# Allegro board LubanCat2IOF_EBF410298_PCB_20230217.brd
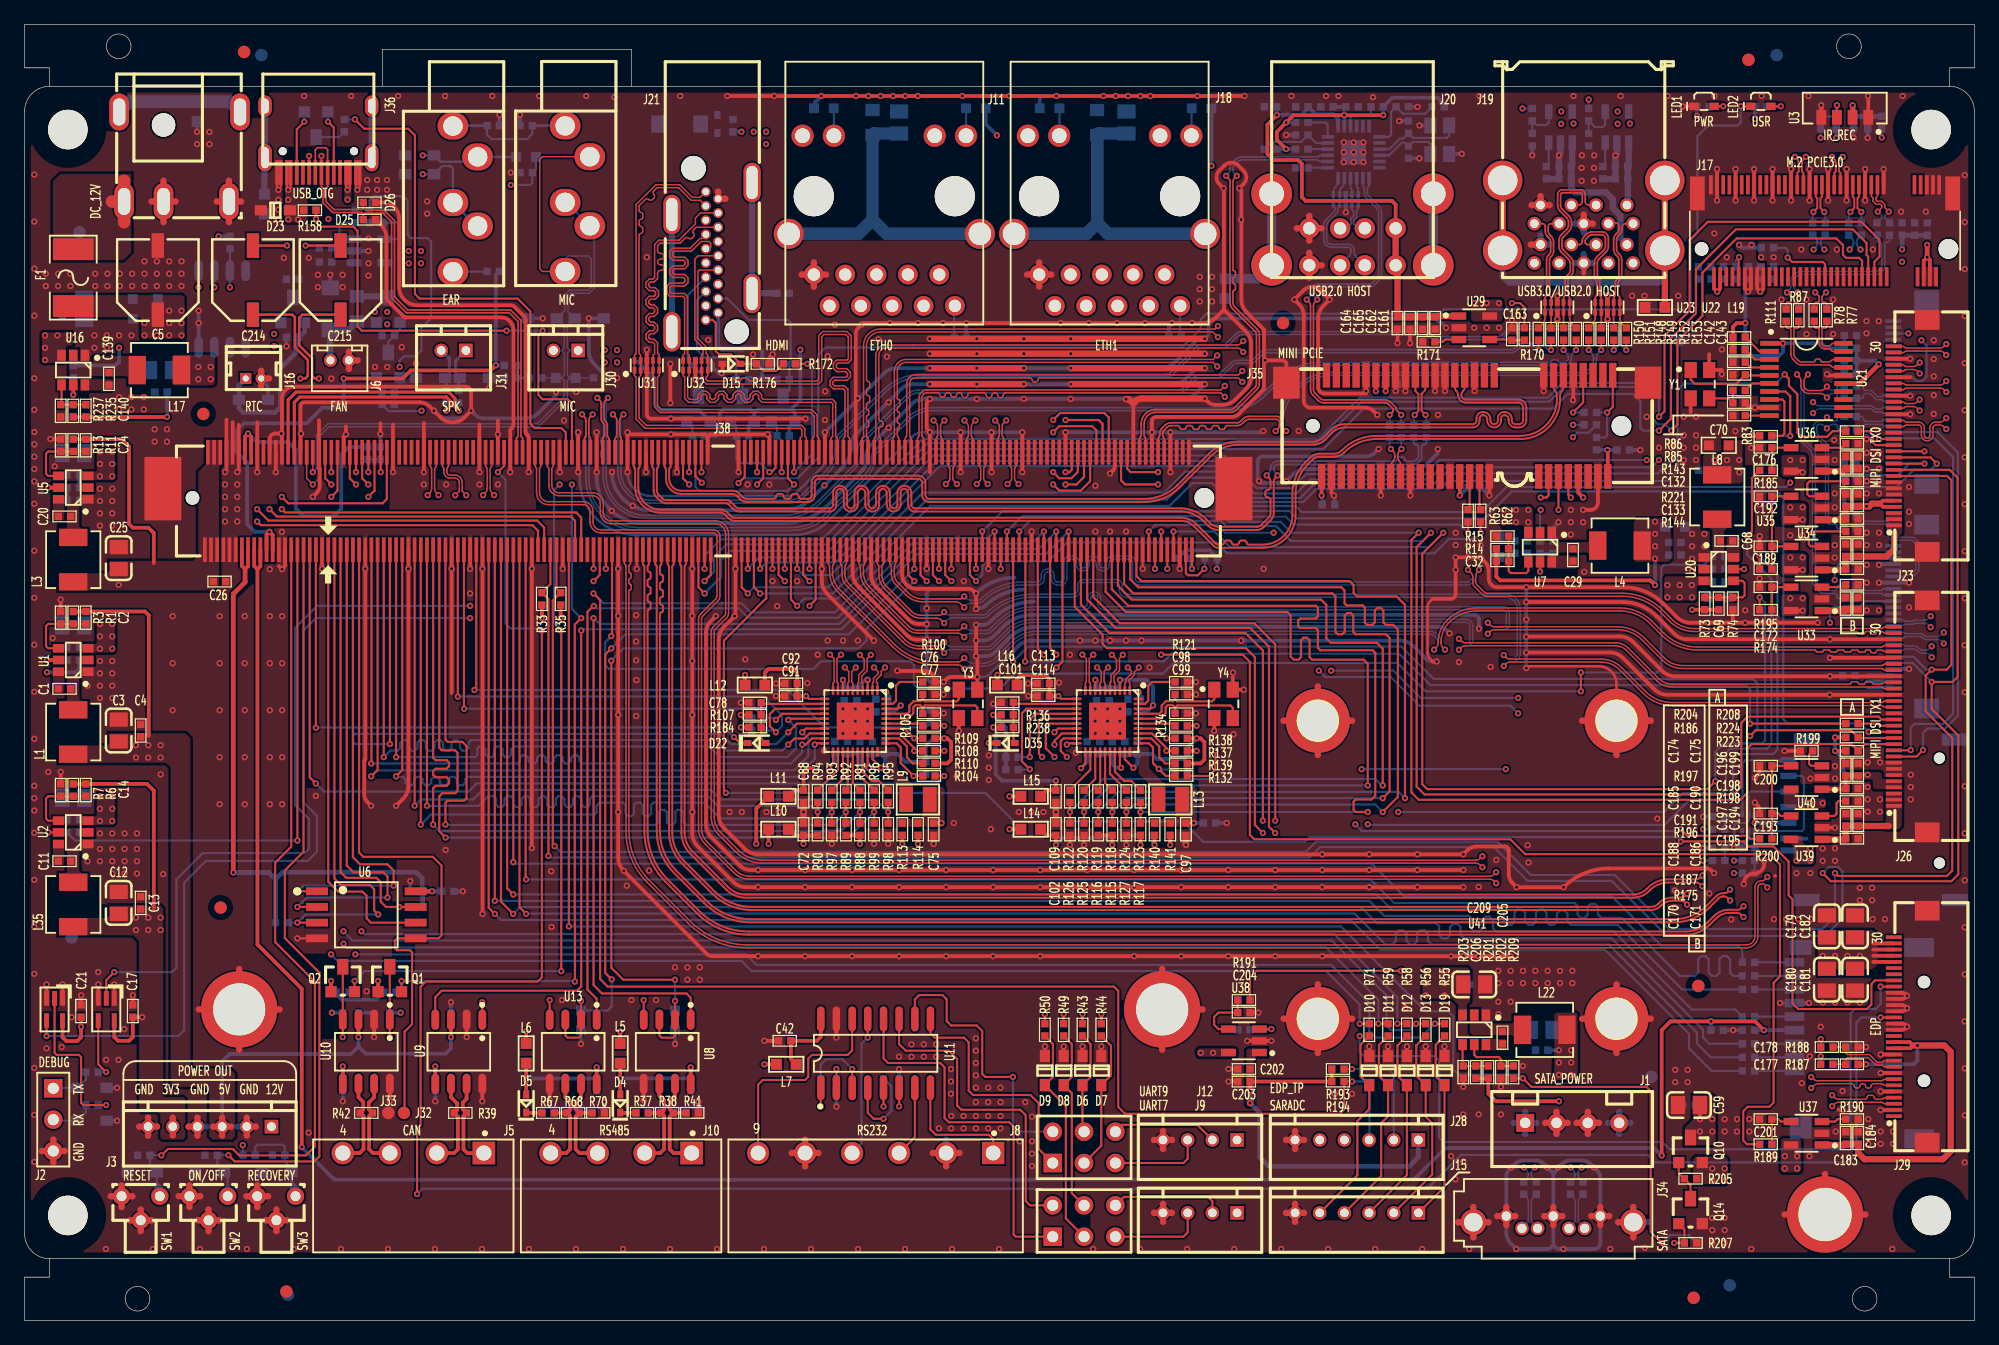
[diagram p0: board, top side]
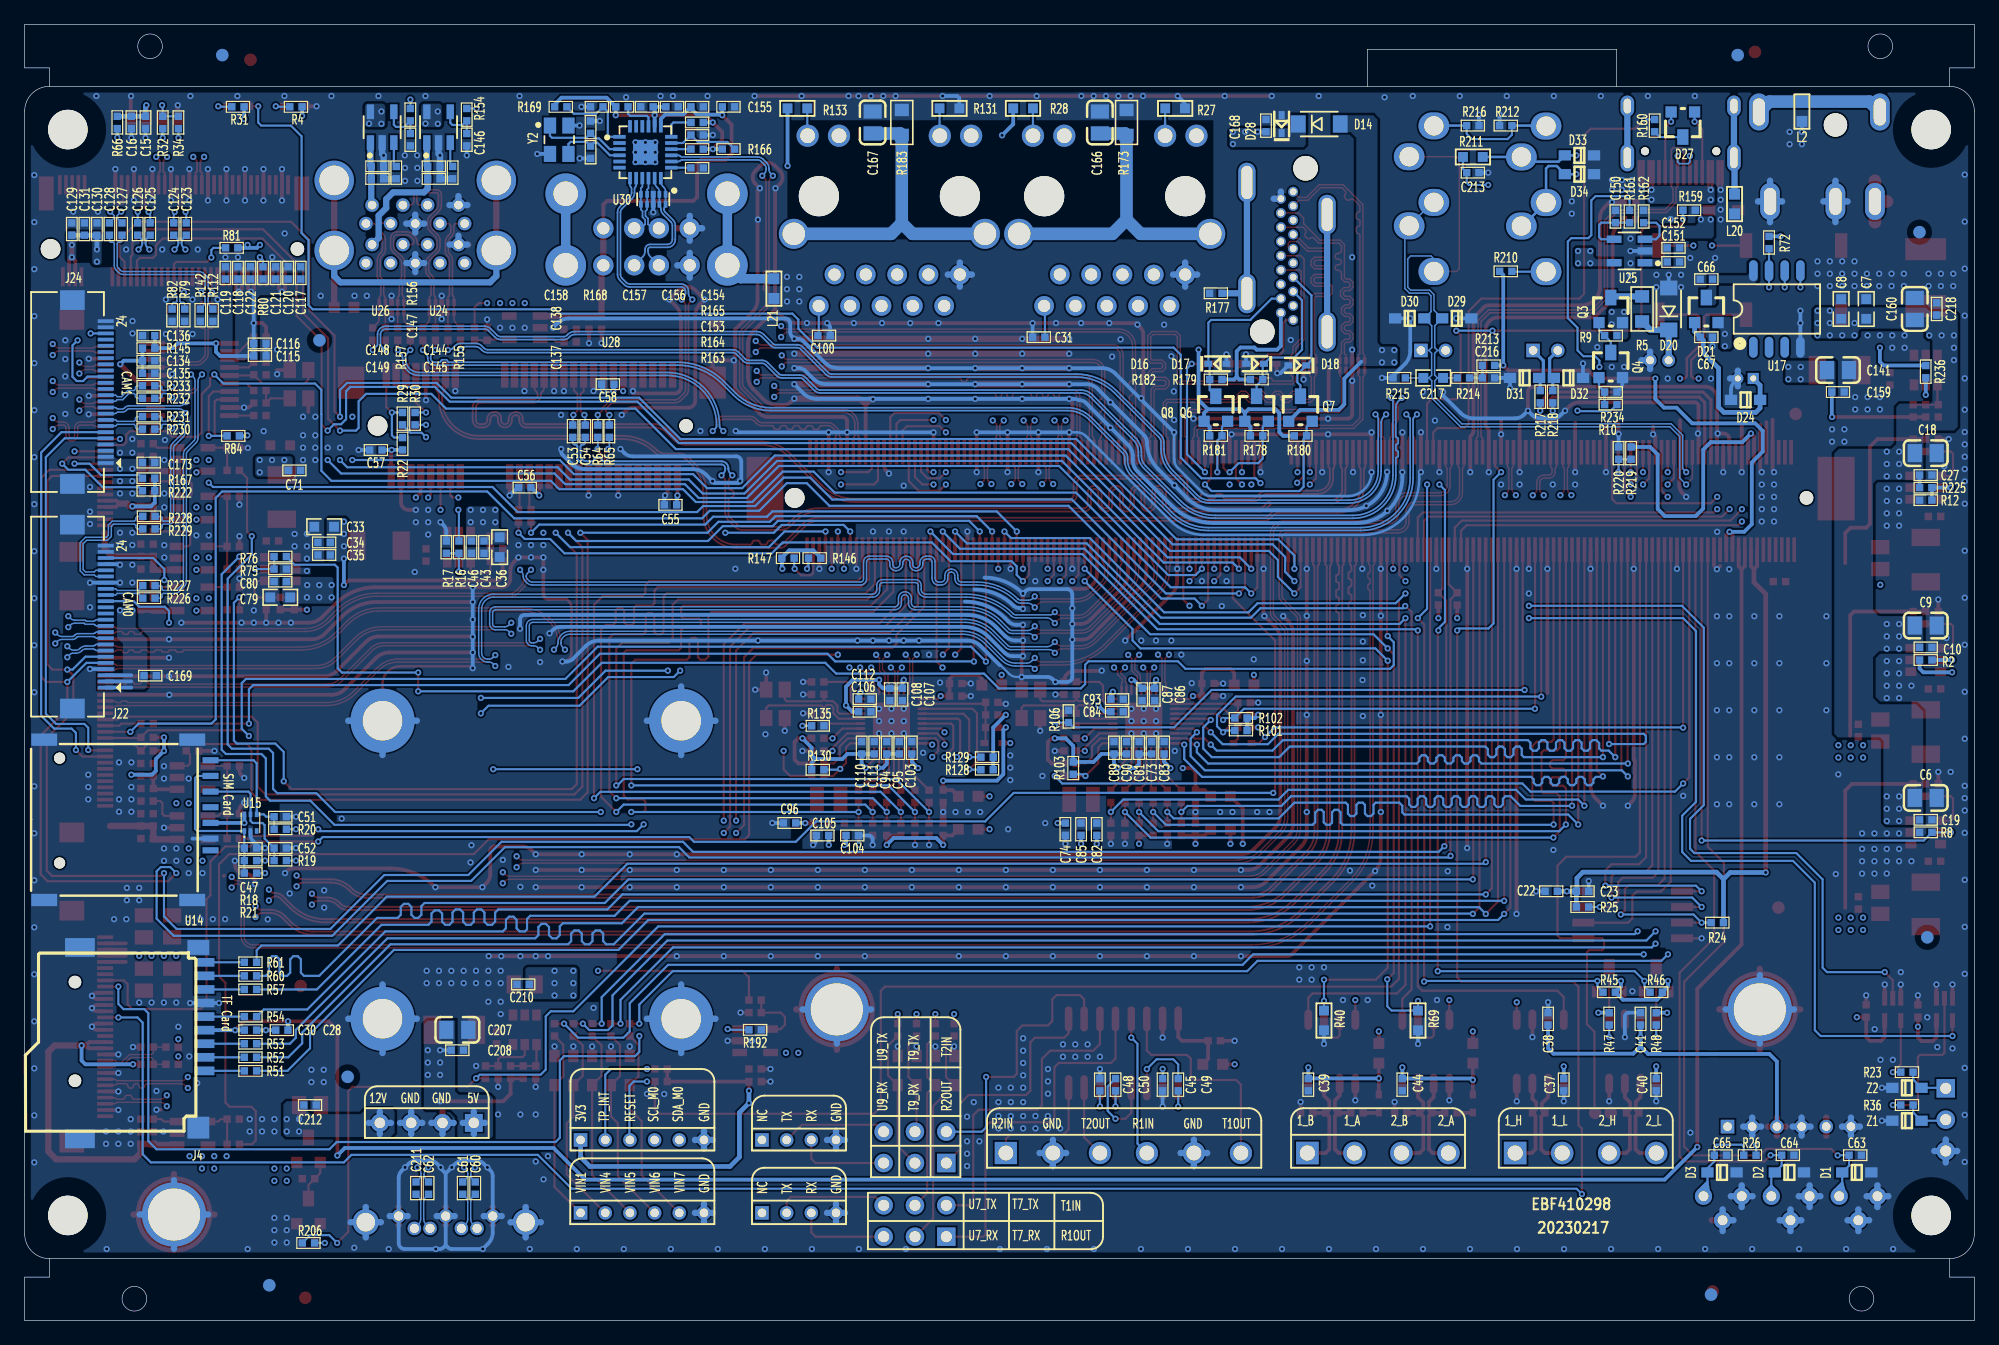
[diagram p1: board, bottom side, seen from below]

Outline 158 x 105 mm; copper layers: TOP, GND02, ART03, ART04, PWR05, BOTTOM. Coordinates in mm from the lower left corner of the outline.
Outline path: circle c7.62,103.25 r1 ; circle c9.14,1.75 r1 ; circle c147.84,103.25 r1 ; circle c149.11,1.75 r1 ; 2,100 arc(0.59,99.41) 0,98 0,7 arc(0.59,5.59) 2,5 ; 2,100 2,101.5 0,101.5 0,105 158,105 158,101.5 156,101.5 156,100 ; 2,100 156,100 ; 2,5 2,3.5 0,3.5 0,0 158,0 158,3.5 156,3.5 156,5 ; 2,5 156,5 ; 156,5 arc(157.41,5.59) 158,7 158,98 arc(157.41,99.41) 156,100 ; 28.99,100 28.99,103 49.18,103 49.18,100

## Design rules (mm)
net group DIFF_MDI0_PHY0: nets MDIN0_PHY0 MDIP0_PHY0
net group DIFF_MDI0_PHY1: nets MDIN0_PHY1 MDIP0_PHY1
net group DIFF_MDI1_PHY0: nets MDIN1_PHY0 MDIP1_PHY0
net group DIFF_MDI1_PHY1: nets MDIN1_PHY1 MDIP1_PHY1
net group DIFF_MDI2_PHY0: nets MDIN2_PHY0 MDIP2_PHY0
net group DIFF_MDI2_PHY1: nets MDIN2_PHY1 MDIP2_PHY1
net group DIFF_MDI3_PHY0: nets MDIN3_PHY0 MDIP3_PHY0
net group DIFF_MDI3_PHY1: nets MDIN3_PHY1 MDIP3_PHY1
net group DIFF_SATA0RX: nets SATA0RXN SATA0RXP
net group DIFF_SATA0TX: nets SATA0TXN SATA0TXP
net group DIFF_USB2_HOST3_D: nets USB2_HOST3_DM USB2_HOST3_DP
net group DIFF_USB3_HOST1_SSTX: nets USB3_HOST1_SSTXN USB3_HOST1_SSTXP
net group DIFF_USB3_OTG0_D: nets USB3_OTG0_DM USB3_OTG0_DP
net group DIFF_USB30_TX: nets USB30_TXN USB30_TXP
net group DIFF_USB_HUB_D1: nets USB_HUB_DM1 USB_HUB_DP1
net group DIFF_USB_HUB_D2: nets USB_HUB_DM2 USB_HUB_DP2
net group EDP_AUXN: nets EDP_AUXN EDP_TX_AUXN
net group EDP_AUXP: nets EDP_AUXP EDP_TX_AUXP
net group GMAC0_RXCLK: nets GMAC0_RXCLK N15580037
net group GMAC0_RXD0: nets GMAC0_RXD0 N15580021
net group GMAC0_RXD1: nets GMAC0_RXD1 N15580025
net group GMAC0_RXD2: nets GMAC0_RXD2 N15580029
net group GMAC0_RXD3: nets GMAC0_RXD3 N15580033
net group GMAC0_RXDV_CRS: nets GMAC0_RXDV_CRS N15580041
net group GMAC1_RXCLK_M1: nets GMAC1_RXCLK_M1 N15599549
net group GMAC1_RXD0_M1: nets GMAC1_RXD0_M1 N15599533
net group GMAC1_RXD1_M1: nets GMAC1_RXD1_M1 N15599537
net group GMAC1_RXD2_M1: nets GMAC1_RXD2_M1 N15599541
net group GMAC1_RXD3_M1: nets GMAC1_RXD3_M1 N15599545
net group GMAC1_RXDV_CRS_M1: nets GMAC1_RXDV_CRS_M1 N15599553
net group MIC1_IN: nets MIC1_INN MIC1_INP
net group N17639713: nets N17639713 N17697748
net group PCIE20_CLKREQN_M1: nets N17411326 PCIE20_CLKREQN_M1
net group PCIE20_TXN: nets PCIE20_TXN PE_TXN
net group PCIE20_TXP: nets PCIE20_TXP PE_TXP
net group PCIE20_WAKEN_M1: nets N17411312 PCIE20_WAKEN_M1
net group PCIE30_REFCLKN_IN: nets N17639523 PCIE30_REFCLKN_IN
net group PCIE30_REFCLKP_IN: nets N17639486 PCIE30_REFCLKP_IN
net group PCIE30_TX0N: nets PCIE30_TX0N PETN0
net group PCIE30_TX0P: nets PCIE30_TX0P PETP0
net group PCIE30_TX1N: nets PCIE30_TX1N PETN1
net group PCIE30_TX1P: nets PCIE30_TX1P PETP1
net group PWM3_IR: nets N17536407 PWM3_IR
net group SDMMC0_CLK: nets N17407474 SDMMC0_CLK
net group SDMMC0_CMD: nets N17407476 SDMMC0_CMD
net group SDMMC0_D0: nets N17407472 SDMMC0_D0
net group SDMMC0_D1: nets N17407480 SDMMC0_D1
net group SDMMC0_D2: nets N17407470 SDMMC0_D2
net group SDMMC0_D3: nets N17407478 SDMMC0_D3
net group USB20_DM1: nets USB2_HOST2_DM USB20_DM1
net group USB20_DP1: nets USB2_HOST2_DP USB20_DP1
net group USB30_DM: nets USB3_HOST1_DM USB30_DM
net group USB30_DP: nets USB3_HOST1_DP USB30_DP
net group USB30_RXN: nets USB3_HOST1_SSRXN USB30_RXN
net group USB30_RXP: nets USB3_HOST1_SSRXP USB30_RXP
net group USB_HUB_DM3: nets N17411507 USB_HUB_DM3
net group USB_HUB_DP3: nets N17411481 USB_HUB_DP3
net group ADC: nets SARADC_VIN1 SARADC_VIN4 SARADC_VIN5 SARADC_VIN6 SARADC_VIN7
net group C_EDP: nets EDP_TX_D0N EDP_TX_D0P EDP_TX_D1N EDP_TX_D1P
net group C_HDMI: nets HDMI_TX0N_PORT HDMI_TX0P_PORT HDMI_TX1N_PORT HDMI_TX1P_PORT HDMI_TX2N_PORT HDMI_TX2P_PORT HDMI_TXCLKN_PORT HDMI_TXCLKP_PORT
net group C_MIPI_DSI_0-3: nets MIPI_DSI_TX0_CLKN MIPI_DSI_TX0_CLKP MIPI_DSI_TX0_D0N MIPI_DSI_TX0_D0P MIPI_DSI_TX0_D1P MIPI_DSI_TX0_D2N MIPI_DSI_TX0_D2P MIPI_DSI_TX0_D3N MIPI_DSI_TX0_D3P
net group C_MIPI_DSI_TX0-3: nets MIPI_DSI_TX1_CLKN MIPI_DSI_TX1_CLKP MIPI_DSI_TX1_D0N MIPI_DSI_TX1_D0P MIPI_DSI_TX1_D1N MIPI_DSI_TX1_D1P MIPI_DSI_TX1_D2N MIPI_DSI_TX1_D2P MIPI_DSI_TX1_D3N MIPI_DSI_TX1_D3P
net group C_MIPICSI: nets MIPI_CSI_RX_CLK0N MIPI_CSI_RX_CLK0P MIPI_CSI_RX_CLK1N MIPI_CSI_RX_CLK1P MIPI_CSI_RX_D0N MIPI_CSI_RX_D0P MIPI_CSI_RX_D1N MIPI_CSI_RX_D1P
net group C_PCLE3R0: nets PCIE30_RX0N PCIE30_RX0P PCIE30_RX1N PCIE30_RX1P
net group GMAC0_TXD0-3: nets GMAC0_TXCLK GMAC0_TXD0 GMAC0_TXD1 GMAC0_TXD2 GMAC0_TXD3 GMAC0_TXEN
net group M_MIPI_DSI_0-3: nets MIPI_DSI_TX0_D1N
net group MIPI_CSI_RX_D2N: nets MIPI_CSI_RX_D2N N17546373 N17737043
net group MIPI_CSI_RX_D2P: nets MIPI_CSI_RX_D2P N17546411 N17737040
net group MIPI_CSI_RX_D3N: nets MIPI_CSI_RX_D3N N17546367 N17737138
net group MIPI_CSI_RX_D3P: nets MIPI_CSI_RX_D3P N17546399 N17737126
net group PCIE: nets PCIE20_REFCLKN PCIE20_REFCLKP PCIE20_RXN PCIE20_RXP
net group PWR: nets 1V05_AVDD_PHY0 1V05_AVDD_PHY1 1V05_DVDD_PHY0 1V05_DVDD_PHY1 1V8_DVDD_PHY0 1V8_DVDD_PHY1 3V3_AVDD_PHY0 3V3_AVDD_PHY1 3V3_DVDD_PHY0 3V3_DVDD_PHY1 HUB_3V3 RS232_3V3 RS485_2_3V3 SIM_VDD VCC3V3_SD VCC5V0_USB20_HOST2 VCC5V0_USB20_HUB VCC5V0_USB30_HOST VCC_1V8 VCCA_1V8 VCCIO_ACODEC VDD_3V3_EDP_LCD VDD_LCD0_3V3
net group REFCLKN: nets N17639617 REF_CLKN REFCLKN
net group REFCLKP: nets N17639615 REF_CLKP REFCLKP
net group SD: nets SDMMC0_DET

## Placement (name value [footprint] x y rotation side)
C1  0.1uF  [C0402]  3.23 51.18 0 top
C2  NC  [C0402]  4.95 56.94 90 top
C3  22uF  [C0805]  7.62 47.8 90 top
C4  0.1uF  [C0402]  9.4 47.8 90 top
C5  100uF  [EC6P3]  10.79 84.3 180 top
C6  22uF  [C0805]  3.94 42.34 180 bottom
C7  4.7uF  [C0603]  8.76 81.96 90 bottom
C8  0.1uF  [C0603]  10.79 81.96 90 bottom
C9  22uF  [C0805]  3.94 56.31 180 bottom
C10  0.1uF  [C0402]  3.94 54.53 180 bottom
C11  0.1uF  [C0402]  3.23 37.21 0 top
C12  22uF  [C0805]  7.62 33.83 90 top
C13  0.1uF  [C0402]  9.4 33.83 90 top
C14  NC  [C0402]  4.95 42.97 90 top
C15  0.1uF  [C0402]  148.21 97.07 270 bottom
C16  4.7uF  [C0402]  149.35 97.07 270 bottom
C17  0.1uF  [C0402]  8.76 25.07 90 top
C18  22uF  [C0805]  3.94 70.28 180 bottom
C19  0.1uF  [C0402]  3.94 40.56 180 bottom
C20  0.1uF  [C0402]  3.23 65.15 0 top
C21  0.1uF  [C0402]  4.57 25.07 90 top
C22  10uF  [C0402]  34.29 34.77 0 bottom
C23  0.1uF  [C0402]  31.75 34.77 180 bottom
C24  NC  [C0402]  4.95 70.91 90 top
C25  22uF  [C0805]  7.62 61.77 90 top
C26  0.1uF  [C0402]  15.79 59.87 0 top
C27  0.1uF  [C0402]  3.94 68.5 180 bottom
C28  10uF  [C0402]  137.16 23.52 0 bottom
C29  0.1uF  [C0402]  125.48 62.02 270 top
C30  0.1uF  [C0402]  139.7 23.52 180 bottom
C31  0.1uF  [C0402]  75.82 79.68 0 bottom
C32  NC  [C0402]  119.76 61.51 0 top
C33  22uF  [C0603]  133.73 64.31 0 bottom
C34  1uF  [C0402]  133.73 63.04 0 bottom
C35  0.1uF  [C0402]  133.73 62.02 0 bottom
C36  22uF  [C0603]  119.51 62.66 270 bottom
C37  0.1uF  [C0402]  33.27 19.1 270 bottom
C38  0.1uF  [C0402]  34.54 24.43 90 bottom
C39  0.1uF  [C0402]  53.98 19.1 270 bottom
C40  0.1uF  [C0402]  25.78 19.1 270 bottom
C41  0.1uF  [C0402]  27.05 24.43 90 bottom
C42  0.1uF  [C0402]  61.59 22.65 180 top
C43  10uF  [C0402]  120.78 62.66 270 bottom
C44  0.1uF  [C0402]  46.35 19.1 270 bottom
C45  0.1uF  [C0402]  65.79 19.1 270 bottom
C46  0.1uF  [C0402]  121.79 62.66 270 bottom
C47  33pF  [C0402]  139.7 38.27 180 bottom
C48  0.1uF  [C0402]  70.87 19.1 90 bottom
C49  0.1uF  [C0402]  64.52 19.1 270 bottom
C50  0.1uF  [C0402]  69.6 19.1 90 bottom
C51  33pF  [C0402]  137.29 40.81 180 bottom
C52  33pF  [C0402]  137.29 38.27 180 bottom
C53  0.1uF  [C0402]  113.59 72.06 90 bottom
C54  0.1uF  [C0402]  112.57 72.06 90 bottom
C55  0.1uF  [C0402]  105.66 66.09 0 bottom
C56  0.1uF  [C0402]  117.47 67.48 0 bottom
C57  0.1uF  [C0402]  129.54 70.53 0 bottom
C58  0.1uF  [C0402]  110.74 75.87 0 bottom
C59  22uF  [C0805]  134.87 17.45 180 top
C60  10nF  [C0402]  121.49 10.71 270 bottom
C61  10nF  [C0402]  122.5 10.71 270 bottom
C62  10nF  [C0402]  125.27 10.71 270 bottom
C63  0.1uF  [C0402]  9.65 13.38 180 bottom
C64  0.1uF  [C0402]  15.11 13.38 180 bottom
C65  0.1uF  [C0402]  20.57 13.38 180 bottom
C66  0.1uF  [C0402]  21.72 84.37 0 bottom
C67  10uF  [C0402]  21.72 79.68 180 bottom
C68  0.1uF  [C0402]  137.92 63.17 180 top
C69  NC  [C0402]  137.29 58.09 270 top
C70  22uF  [C0603]  137.29 70.91 180 top
C71  0.1uF  [C0402]  136.14 68.88 180 bottom
C72  0.1uF  [C0402]  63.12 39.8 90 top
C73  0.1uF  [C0402]  66.67 46.4 90 bottom
C74  0.1uF  [C0402]  73.66 39.8 270 bottom
C75  4.7uF  [C0402]  73.66 39.8 270 top
C76  18pF  [C0402]  73.28 50.72 0 top
C77  18pF  [C0402]  73.28 49.2 0 top
C78  0.1uF  [C0402]  59.18 50.06 180 top
C79  22uF  [C0603]  137.29 58.59 0 bottom
C80  0.1uF  [C0402]  137.29 59.86 0 bottom
C81  0.1uF  [C0402]  67.69 46.4 90 bottom
C82  0.1uF  [C0402]  71.12 39.8 90 bottom
C83  0.1uF  [C0402]  65.66 46.4 90 bottom
C84  0.1uF  [C0402]  69.47 49.32 180 bottom
C85  0.1uF  [C0402]  72.39 39.8 90 bottom
C86  0.1uF  [C0402]  66.42 50.72 270 bottom
C87  0.1uF  [C0402]  67.44 50.72 270 bottom
C88  0.1uF  [C0402]  63.12 42.46 270 top
C89  0.1uF  [C0402]  69.72 46.4 90 bottom
C90  0.1uF  [C0402]  68.71 46.4 90 bottom
C91  0.1uF  [C0402]  62.1 50.59 180 top
C92  0.1uF  [C0402]  62.1 51.61 180 top
C93  0.1uF  [C0402]  69.47 50.34 180 bottom
C94  0.1uF  [C0402]  88.14 46.4 90 bottom
C95  0.1uF  [C0402]  87.12 46.4 90 bottom
C96  0.1uF  [C0402]  96.01 40.31 0 bottom
C97  4.7uF  [C0402]  94.11 39.8 270 top
C98  18pF  [C0402]  93.73 50.72 0 top
C99  18pF  [C0402]  93.73 49.2 0 top
C100  0.1uF  [C0402]  93.22 79.8 180 bottom
C101  0.1uF  [C0402]  79.63 50.08 180 top
C102  0.1uF  [C0402]  83.57 39.8 90 top
C103  0.1uF  [C0402]  86.11 46.4 90 bottom
C104  0.1uF  [C0402]  90.93 39.29 180 bottom
C105  0.1uF  [C0402]  93.34 39.29 0 bottom
C106  0.1uF  [C0402]  89.92 49.32 180 bottom
C107  0.1uF  [C0402]  86.87 50.72 270 bottom
C108  0.1uF  [C0402]  87.88 50.72 270 bottom
C109  0.1uF  [C0402]  83.57 42.46 270 top
C110  0.1uF  [C0402]  90.17 46.4 90 bottom
C111  0.1uF  [C0402]  89.15 46.4 90 bottom
C112  0.1uF  [C0402]  89.92 50.34 180 bottom
C113  0.1uF  [C0402]  82.55 51.61 180 top
C114  0.1uF  [C0402]  82.55 50.59 180 top
C115  1uF  [C0402]  138.94 78.15 180 bottom
C116  0.1uF  [C0402]  138.94 79.17 180 bottom
C117  0.1uF  [C0402]  135.64 84.88 90 bottom
C118  0.1uF  [C0402]  140.72 84.88 90 bottom
C119  0.1uF  [C0402]  141.73 84.88 90 bottom
C120  0.1uF  [C0402]  136.65 84.88 90 bottom
C121  0.1uF  [C0402]  137.67 84.88 90 bottom
C122  0.1uF  [C0402]  139.7 84.88 90 bottom
C123  0.22uF  [C0402]  144.91 88.44 90 bottom
C124  0.22uF  [C0402]  145.92 88.44 90 bottom
C125  0.22uF  [C0402]  147.83 88.44 90 bottom
C126  0.22uF  [C0402]  148.84 88.44 90 bottom
C127  0.22uF  [C0402]  150.11 88.44 90 bottom
C128  0.22uF  [C0402]  151.13 88.44 90 bottom
C129  0.1uF  [C0402]  154.18 88.44 90 bottom
C130  0.1uF  [C0402]  152.15 88.44 90 bottom
C131  0.1uF  [C0402]  153.16 88.44 90 bottom
C132  18pF  [C0402]  138.94 76.63 180 top
C133  18pF  [C0402]  138.94 74.34 0 top
C134  0.1uF  [C0402]  147.96 77.77 180 bottom
C135  1uF  [C0402]  147.96 76.75 180 bottom
C136  4.7uF  [C0402]  147.96 79.8 0 bottom
C137  NC  [C0402]  112.14 94.66 270 bottom
C138  NC  [C0402]  112.14 96.69 90 bottom
C139  0.1uF  [C0402]  6.83 76.3 90 top
C140  NC  [C0402]  4.95 73.71 270 top
C141  22uF  [C0805]  11.05 77.01 180 bottom
C142  0.1uF  [C0402]  128.78 79.93 270 top
C143  0.1uF  [C0402]  129.79 79.93 270 top
C144  10uF  [C0402]  124.84 93.52 180 bottom
C145  0.1uF  [C0402]  124.84 92.5 180 bottom
C146  0.1uF  [C0402]  122.17 95.68 270 bottom
C147  0.1uF  [C0402]  126.75 95.68 270 bottom
C148  10uF  [C0402]  129.41 93.52 180 bottom
C149  0.1uF  [C0402]  129.41 92.5 180 bottom
C150  0.1uF  [C0402]  29.08 89.45 90 bottom
C151  10uF  [C0402]  24.38 85.77 180 bottom
C152  0.1uF  [C0402]  24.38 86.91 180 bottom
C153  0.1uF  [C0402]  103.5 96.06 180 bottom
C154  10uF  [C0402]  103.5 98.34 180 bottom
C155  0.1uF  [C0402]  100.97 98.34 180 bottom
C156  0.1uF  [C0402]  105.54 98.34 180 bottom
C157  10uF  [C0402]  107.57 98.34 0 bottom
C158  10nF  [C0402]  111.63 98.34 0 bottom
C159  0.1uF  [C0402]  11.05 75.23 180 bottom
C160  22uF  [C0805]  4.83 81.96 90 bottom
C161  10uF  [C0402]  114.3 80.82 270 top
C162  0.1uF  [C0402]  113.28 80.82 270 top
C163  0.1uF  [C0402]  120.52 79.93 90 top
C164  1uF  [C0402]  111.25 80.82 270 top
C165  1uF  [C0402]  112.27 80.82 270 top
C166  1nF  [C0805]  70.87 97.07 90 bottom
C167  1nF  [C0805]  89.28 97.07 90 bottom
C168  1uF  [C0402]  57.4 96.82 90 bottom
C169  10uF  [C0402]  147.83 52.24 180 bottom
C170  10uF  [C0402]  147.57 58.09 90 top
C171  0.1uF  [C0402]  148.59 58.09 90 top
C172  0.1uF  [C0402]  141.1 59.42 180 top
C173  10uF  [C0402]  147.96 69.52 180 bottom
C174  10uF  [C0402]  147.57 69.52 90 top
C175  0.1uF  [C0402]  148.59 69.52 90 top
C176  0.1uF  [C0402]  141.1 70.72 180 top
C177  0.1uF  [C0402]  146.05 20.75 0 top
C178  0.1uF  [C0402]  146.05 22.14 0 top
C179  10uF  [C0805]  146.05 31.92 90 top
C180  10uF  [C0805]  146.05 27.61 270 top
C181  10uF  [C0805]  148.34 27.61 270 top
C182  10uF  [C0805]  148.34 31.92 90 top
C183  10uF  [C0402]  147.57 14.78 90 top
C184  0.1uF  [C0402]  148.59 14.78 90 top
C185  0.1uF  [C0402]  147.57 66.47 90 top
C186  10uF  [C0402]  148.59 62.4 90 top
C187  10uF  [C0402]  148.08 60.88 0 top
C188  0.1uF  [C0402]  147.57 62.4 90 top
C189  0.1uF  [C0402]  141.1 62.72 180 top
C190  10uF  [C0402]  148.59 66.47 90 top
C191  0.1uF  [C0402]  148.08 64.94 0 top
C192  0.1uF  [C0402]  141.1 66.78 180 top
C193  0.1uF  [C0402]  141.1 41.07 180 top
C194  10uF  [C0402]  148.59 40.56 90 top
C195  0.1uF  [C0402]  148.08 39.04 0 top
C196  0.1uF  [C0402]  147.57 44.62 90 top
C197  10uF  [C0402]  147.57 40.56 90 top
C198  0.1uF  [C0402]  148.08 43.1 0 top
C199  10uF  [C0402]  148.59 44.62 90 top
C200  0.1uF  [C0402]  141.1 44.94 180 top
C201  0.1uF  [C0402]  141.1 16.3 180 top
C202  10uF  [C0402]  98.81 20.37 180 top
C203  0.1uF  [C0402]  98.81 19.35 180 top
C204  0.1uF  [C0402]  98.81 24.94 0 top
C205  0.1uF  [C0402]  119.76 22.91 90 top
C206  NC  [C0402]  117.6 20.11 270 top
C207  22uF  [C0805]  122.94 23.54 180 bottom
C208  0.1uF  [C0402]  122.94 21.89 180 bottom
C209  22uF  [C0805]  117.47 27.22 0 top
C210  0.1uF  [C0402]  117.6 27.22 0 bottom
C211  10nF  [C0402]  126.29 10.71 270 bottom
C212  0.1uF  [C0402]  134.87 17.45 180 bottom
C213  1uF  [C0402]  40.64 93.01 180 bottom
C214  220uF  [EC6P3]  18.5 84.3 180 top
C215  220uF  [EC6P3]  25.6 84.3 180 top
C216  1uF  [C0402]  39.37 76.37 180 bottom
C217  100pF  [C0603]  43.85 76.37 0 bottom
C218  0.1uF  [C0402]  3.05 81.96 90 bottom
D1  PESD3V3L1BA  [SOD323]  9.53 11.98 180 bottom
D2  PESD3V3L1BA  [SOD323]  14.99 11.98 180 bottom
D3  PESD3V3L1BA  [SOD323]  20.45 11.98 180 bottom
D4  RB521S30  [SOD523]  48.26 17.57 90 top
D5  RB521S30  [SOD523]  40.64 17.57 90 top
D6  PESD3V3L1BA  [SOD323]  85.72 20.24 270 top
D7  PESD3V3L1BA  [SOD323]  87.25 20.24 270 top
D8  PESD3V3L1BA  [SOD323]  84.2 20.24 270 top
D9  PESD3V3L1BA  [SOD323]  82.68 20.24 270 top
D10  PESD3V3L1BA  [SOD323]  108.97 20.24 270 top
D11  PESD3V3L1BA  [SOD323]  110.49 20.24 270 top
D12  PESD3V3L1BA  [SOD323]  112.01 20.24 270 top
D13  PESD3V3L1BA  [SOD323]  113.54 20.24 270 top
D14  1N5819W  [SOD-123]  53.09 96.95 0 bottom
D15  ESD5B5.0ST1G  [SOD523]  57.28 77.52 180 top
D16  ESD5B5.0ST1G  [SOD523]  61.34 77.52 180 bottom
D17  ESD5B5.0ST1G  [SOD523]  58.29 77.52 0 bottom
D18  ESD5B5.0ST1G  [SOD523]  54.86 77.39 0 bottom
D19  PESD3V3L1BA  [SOD323]  115.06 20.24 270 top
D20  1N4148W  [SOD-123]  24.77 81.96 270 bottom
D21  BAT54C  [SOT23]  21.72 81.85 180 bottom
D22  RB521S30  [SOD523]  59.31 46.78 0 top
D23  PESD5V0S1BA-N  [SOD323]  20.32 89.96 0 top
D24  PESD3V3L1BA  [SOD323]  18.54 74.6 0 bottom
D25  KLXES15AAA1  [ES0402]  27.94 89.2 0 top
D26  KLXES15AAA1  [ES0402]  27.94 90.6 0 top
D27  BAT54A  [SOT23]  23.62 96.94 0 bottom
D28  ESD5B5.0ST1G  [SOD523]  56.13 96.95 90 bottom
D29  PESD3V3L1BA  [SOD323]  41.94 81.2 0 bottom
D30  PESD3V3L1BA  [SOD323]  45.75 81.2 180 bottom
D31  PESD3V3L1BA  [SOD323]  36.45 76.37 180 bottom
D32  PESD3V3L1BA  [SOD323]  32.89 76.37 0 bottom
D33  PESD3V3L1BA  [SOD323]  32 94.41 0 bottom
D34  PESD3V3L1BA  [SOD323]  32 92.88 0 bottom
D35  RB521S30  [SOD523]  79.5 46.78 0 top
F1  SMD1812P200TF16  [F1812]  3.94 84.5 270 top
J1  CON4  [XH2P54-4P]  125.41 16 0 top
J2  1X3PIN-M  [DIP_3P_2P54]  2.32 16.26 270 top
J3  PH-6A  [PH-1X6-2P0]  15 15.7 180 top
J4  TF_Card  [TFCARD]  153.92 23.41 270 bottom
J5  CON4  [DB2ERC-3P81-4P]  31.5 13.56 180 top
J6  A1501WV-2P  [ZH1P5MM_TH_2P]  25.53 77.8 0 top
J8  CON6  [DB2ERC-3P81-6P]  68.96 13.56 180 top
J9  PH-4A  [PH-1X4-2P0]  95.25 8.71 180 top
J10  CON4  [DB2ERC-3P81-4P]  48.33 13.56 180 top
J11  -  [HY911130A]  69.66 91.1 0 top
J12  PH-4A  [PH-1X4-2P0]  95.25 14.62 180 top
J13  2X3PIN-M  [DIP-2X3-2P54]  85.85 8.05 0 top
J14  2X3PIN-M  [DIP-2X3-2P54]  85.85 14.02 0 top
J15  PH-6A  [PH-1X6-2P0]  107.95 8.71 180 top
J16  1.25T-2A  [GH1P25_TH_2P]  18.54 76.33 0 top
J17  -  [M2_NGFF_M_KEY]  145.9 88.3 0 top
J18  -  [HY911130A]  87.92 91.1 0 top
J19  USB3D0_USB2D0-A-D  [USB3D0-AF-18P]  126.35 88.88 180 top
J20  -  [USB-A-D]  107.6 92 0 top
J21  HDMI-001C  [HDMI-SMD]  55.7 86.16 90 top
J22  -  [FPC_24P_0P5]  152.78 57.03 90 bottom
J23  -  [FPC-30P-0P5]  152.83 71.67 90 top
J24  -  [FPC_24P_0P5]  152.78 75.23 90 bottom
J25  PJ-325C5-G  [EAR_JACK]  34.71 90.58 270 top
J26  -  [FPC-30P-0P5]  152.83 48.94 90 top
J27  PJ-325C5-R  [EAR_JACK]  43.8 90.6 270 top
J28  PH-6A  [PH-1X6-2P0]  107.95 14.62 180 top
J29  -  [FPC-30P-0P5]  152.83 23.8 90 top
J30  PH  [PH-1X2-2P0_L]  43.85 78.6 180 top
J31  PH  [PH-1X2-2P0_L]  34.76 78.6 180 top
J32  TP  [TP_1MM]  30.73 16.81 0 top
J33  TP  [TP_1MM]  29.46 16.81 0 top
J34  SATA  [SSATA_V]  123.88 8.45 0 top
J35  MINI-PCIE  [PCIE_52P]  116.9 72.49 180 top
J36  TYPE-C  [TYPE-C-31-M-12]  23.8 93.31 180 top
J38  -  [AS0B821-S55B-7H]  54.6 66.4 0 top
J39  DC-044A-20A  [DC_IN_TH_3P_10R1X11R6]  12.55 94.3 270 top
L1  3.3uH  [L4520]  3.93 47.67 270 top
L2  100R 100MHz  [L0603]  13.97 97.96 270 bottom
L3  3.3uH  [L4520]  3.93 61.64 270 top
L4  3.3uH  [L4520]  129.28 62.78 0 top
L5  100R 100MHz  [L0603]  48.26 21.64 270 top
L6  100R 100MHz  [L0603]  40.64 21.64 270 top
L7  100R 100MHz  [L0603]  61.72 20.75 180 top
L8  3.3uH  [L4520]  137.16 66.72 90 top
L9  2.2uH  [L2520]  72.39 42.21 0 top
L10  100R 100MHz  [L0603]  61.09 39.8 180 top
L11  100R 100MHz  [L0603]  61.09 42.46 180 top
L12  100R 100MHz  [L0603]  59.18 51.48 180 top
L13  2.2uH  [L2520]  92.84 42.21 0 top
L14  100R 100MHz  [L0603]  81.53 39.8 180 top
L15  100R 100MHz  [L0603]  81.53 42.46 180 top
L16  100R 100MHz  [L0603]  79.63 51.48 180 top
L17  3.3uH  [L4520]  10.92 77.01 0 top
L19  100R 100MHz  [L0603]  132.12 82.09 180 top
L20  100R 100MHz  [L0603]  19.43 90.47 270 bottom
L21  100R 100MHz  [L0603]  97.28 83.61 270 bottom
L22  3.3uH  [L4520]  123.19 23.54 0 top
L35  3.3uH  [L4520]  3.93 33.7 270 top
LED1  HS-0602-UR  [LED_HS_0602_UR]  136.1 98.39 0 top
LED2  HS-0602-UG  [LED_HS_0602_UR]  140.7 98.39 0 top
NOREF  -  [unnamed]  21.21 2.33 0 top
NOREF#2  -  [unnamed]  15.88 33.45 0 top
NOREF#3  -  [unnamed]  135.25 1.82 0 top
NOREF#4  -  [#2]  77.79 104.55 0 top
NOREF#5  -  [#2]  47.91 102.02 0 top
NOREF#6  -  [#2]  59.53 102 0 top
NOREF#7  -  [unnamed]  14.48 73.45 0 top
NOREF#8  -  [unnamed]  135.64 27.1 0 top
NOREF#9  -  [unnamed]  139.7 102.15 0 top
NOREF#10  -  [#2]  96.05 104.55 0 top
NOREF#11  -  [unnamed]  17.78 102.79 0 top
NOREF#12  -  [#2]  2 5 90 top
NOREF#13  -  [#2]  0 7.1 0 top
NOREF#14  -  [#2]  114.15 102 0 top
NOREF#15  -  [unnamed]  101.98 80.82 0 top
NOREF#16  -  [unnamed]  3.81 31.03 180 bottom
NOREF#17  -  [unnamed]  138.18 2.84 180 bottom
NOREF#18  -  [unnamed]  131.83 19.73 180 bottom
NOREF#19  -  [unnamed]  141.99 102.54 180 bottom
NOREF#20  -  [unnamed]  4.45 88.18 180 bottom
NOREF#21  -  [unnamed]  134.11 79.42 180 bottom
NOREF#22  -  [unnamed]  19.18 102.54 180 bottom
NOREF#23  -  [unnamed]  21.34 2.08 180 bottom
Q1  2SK3018  [SOT23]  29.59 27.62 0 top
Q2  2SK3018  [SOT23]  25.78 27.62 0 top
Q3  SSM3J328R-LF  [SOT23]  29.46 81.85 180 bottom
Q4  SS8050  [SOT23]  29.46 77.39 180 bottom
Q6  2SK3018  [SOT23]  58.17 73.85 180 bottom
Q7  2SK3018  [SOT23]  54.61 73.85 180 bottom
Q8  2SK3018  [SOT23]  61.47 73.85 180 bottom
Q10  SSM3J328R-LF  [SOT23]  135 13.78 0 top
Q14  2SK3018  [SOT23]  135 8.82 0 top
R1  115K  [R0402]  3.94 56.94 90 top
R2  1K  [R0402]  3.94 53.51 0 bottom
R3  20K  [R0402]  2.92 56.94 90 top
R4  5.1K  [R0402]  136.02 98.34 0 bottom
R5  10R  [R0805]  26.92 81.96 270 bottom
R6  100K  [R0402]  3.94 42.97 90 top
R7  30K  [R0402]  2.92 42.97 90 top
R8  1K  [R0402]  3.94 39.54 0 bottom
R9  10K  [R0402]  29.46 79.8 0 bottom
R10  1K  [R0402]  29.46 74.21 0 bottom
R11  115K  [R0402]  3.94 70.91 90 top
R12  27K  [R0402]  3.94 66.47 0 bottom
R13  20K  [R0402]  2.92 70.91 90 top
R14  100K  [R0402]  119.76 62.53 0 top
R15  30K  [R0402]  119.76 63.55 180 top
R16  1K  [R0402]  122.81 62.66 270 bottom
R17  10K  [R0402]  123.83 62.66 90 bottom
R18  15K  [R0402]  139.7 37.26 0 bottom
R19  0R  [R0402]  137.29 37.26 0 bottom
R20  0R  [R0402]  137.29 39.8 0 bottom
R21  0R  [R0402]  139.7 36.24 0 bottom
R22  4.7K  [R0402]  127.38 71.04 90 bottom
R23  100R  [R0402]  5.46 20.11 0 bottom
R24  10K  [R0402]  20.83 32.23 0 bottom
R25  10K  [R0402]  31.75 33.5 180 bottom
R26  100R  [R0402]  18.19 13.38 180 bottom
R27  510R  [R0603]  64.77 98.22 180 bottom
R28  510R  [R0603]  77.09 98.22 0 bottom
R29  22R  [R0402]  127.38 73.07 90 bottom
R30  22R  [R0402]  126.36 73.07 90 bottom
R31  4.7K  [R0402]  140.72 98.34 0 bottom
R32  10K  [R0402]  146.81 97.07 90 bottom
R33  2.2K  [R0402]  41.91 58.47 90 top
R34  22R  [R0402]  145.54 97.07 90 bottom
R35  2.2K  [R0402]  43.43 58.47 90 top
R36  100R  [R0402]  5.46 17.45 0 bottom
R37  4.7K  [R0402]  50.04 16.81 180 top
R38  120R  [R0402]  52.07 16.81 180 top
R39  120R  [R0402]  35.31 16.81 180 top
R40  10K  [R0603]  52.7 24.3 270 bottom
R41  4.7K  [R0402]  54.1 16.81 0 top
R42  120R  [R0402]  27.69 16.81 180 top
R43  100R  [R0402]  85.72 23.54 270 top
R44  100R  [R0402]  87.25 23.54 270 top
R45  10K  [R0402]  29.59 26.59 0 bottom
R46  10K  [R0402]  25.78 26.59 0 bottom
R47  10K  [R0402]  29.59 24.43 270 bottom
R48  10K  [R0402]  25.78 24.43 270 bottom
R49  100R  [R0402]  84.2 23.54 270 top
R50  100R  [R0402]  82.68 23.54 270 top
R51  22R  [R0402]  139.7 20.22 0 bottom
R52  22R  [R0402]  139.7 21.32 0 bottom
R53  22R  [R0402]  139.7 22.41 0 bottom
R54  22R  [R0402]  139.7 24.62 0 bottom
R55  100R  [R0402]  115.06 23.54 270 top
R56  100R  [R0402]  113.54 23.54 270 top
R57  22R  [R0402]  139.7 26.81 0 bottom
R58  100R  [R0402]  112.01 23.54 270 top
R59  100R  [R0402]  110.49 23.54 270 top
R60  22R  [R0402]  139.7 27.92 0 bottom
R61  0R  [R0402]  139.7 29.02 0 bottom
R62  1K  [R0402]  117.98 65.2 270 top
R63  1K  [R0402]  116.97 65.2 270 top
R64  2.2R  [R0402]  111.56 72.06 90 bottom
R65  2.2R  [R0402]  110.62 72.06 90 bottom
R66  22R  [R0402]  150.5 97.07 270 bottom
R67  4.7K  [R0402]  42.42 16.81 180 top
R68  120R  [R0402]  44.45 16.81 180 top
R69  10K  [R0603]  45.09 24.3 270 bottom
R70  4.7K  [R0402]  46.48 16.81 0 top
R71  100R  [R0402]  108.97 23.54 270 top
R72  4.7K  [R0402]  16.64 87.35 270 bottom
R73  100K  [R0402]  136.14 58.09 270 top
R74  30K  [R0402]  138.43 58.09 270 top
R75  10K  [R0402]  137.29 60.88 180 bottom
R76  1K  [R0402]  137.29 61.9 180 bottom
R77  33R  [R0402]  146.05 81.45 90 top
R78  33R  [R0402]  145.03 81.45 90 top
R79  49.9R  [R0402]  145.03 81.45 270 bottom
R80  10K  [R0402]  138.68 84.88 270 bottom
R81  10K  [R0402]  141.22 86.91 180 bottom
R82  49.9R  [R0402]  146.05 81.45 270 bottom
R83  10K  [R0402]  141.1 71.67 0 top
R84  4.7K  [R0402]  141.1 71.67 0 bottom
R85  10K  [R0402]  138.94 78.66 0 top
R86  10K  [R0402]  138.94 79.68 0 top
R87  33R  [R0402]  143.76 81.45 90 top
R88  4.7K  [R0402]  67.69 39.8 90 top
R89  4.7K  [R0402]  66.55 39.8 90 top
R90  4.7K  [R0402]  64.26 39.8 90 top
R91  22R  [R0402]  67.69 42.46 90 top
R92  22R  [R0402]  66.55 42.46 90 top
R93  22R  [R0402]  65.41 42.46 90 top
R94  22R  [R0402]  64.26 42.46 90 top
R95  22R  [R0402]  69.98 42.46 90 top
R96  22R  [R0402]  68.83 42.46 90 top
R97  4.7K  [R0402]  65.41 39.8 270 top
R98  4.7K  [R0402]  69.98 39.8 270 top
R99  4.7K  [R0402]  68.83 39.8 270 top
R100  2.49K  [R0402]  73.28 51.74 0 top
R101  4.7K  [R0402]  59.44 47.8 0 bottom
R102  4.7K  [R0402]  59.44 48.81 0 bottom
R103  4.7K  [R0402]  73.03 44.75 270 bottom
R104  NC  [R0402]  73.28 44.12 180 top
R105  100R  [R0402]  73.28 48.18 180 top
R106  120R  [R0402]  73.41 48.94 90 bottom
R107  10K  [R0402]  59.18 49.07 0 top
R108  4.7K  [R0402]  73.28 46.15 0 top
R109  4.7K  [R0402]  73.28 47.16 0 top
R110  4.7K  [R0402]  73.28 45.13 0 top
R111  33R  [R0402]  142.75 81.45 90 top
R112  49.9R  [R0402]  142.75 81.45 270 bottom
R113  0R  [R0402]  71.12 39.8 90 top
R114  0R  [R0402]  72.39 39.8 270 top
R115  4.7K  [R0402]  88.14 39.8 90 top
R116  4.7K  [R0402]  87 39.8 90 top
R117  4.7K  [R0402]  90.42 39.8 90 top
R118  22R  [R0402]  88.14 42.46 90 top
R119  22R  [R0402]  87 42.46 90 top
R120  22R  [R0402]  85.85 42.46 90 top
R121  2.49K  [R0402]  93.73 51.74 0 top
R122  22R  [R0402]  84.71 42.46 90 top
R123  22R  [R0402]  90.42 42.46 90 top
R124  22R  [R0402]  89.28 42.46 90 top
R125  4.7K  [R0402]  85.85 39.8 270 top
R126  4.7K  [R0402]  84.71 39.8 270 top
R127  4.7K  [R0402]  89.28 39.8 270 top
R128  4.7K  [R0402]  80.01 44.62 0 bottom
R129  4.7K  [R0402]  80.01 45.64 0 bottom
R130  4.7K  [R0402]  93.73 44.62 180 bottom
R131  510R  [R0603]  83.06 98.22 180 bottom
R132  NC  [R0402]  93.73 44.12 180 top
R133  510R  [R0603]  95.38 98.22 0 bottom
R134  100R  [R0402]  93.73 48.18 180 top
R135  120R  [R0402]  93.73 48.18 180 bottom
R136  10K  [R0402]  79.63 49.07 0 top
R137  4.7K  [R0402]  93.73 46.15 0 top
R138  4.7K  [R0402]  93.73 47.16 0 top
R139  4.7K  [R0402]  93.73 45.13 0 top
R140  0R  [R0402]  91.57 39.8 90 top
R141  0R  [R0402]  92.84 39.8 270 top
R142  49.9R  [R0402]  143.76 81.45 270 bottom
R143  10K  [R0402]  138.94 77.64 180 top
R144  470R  [R0402]  138.94 73.33 180 top
R145  2.2R  [R0402]  147.96 78.79 180 bottom
R146  2.2K  [R0402]  93.98 61.77 0 bottom
R147  2.2K  [R0402]  96.14 61.77 180 bottom
R148  2.2R  [R0402]  124.71 79.93 270 top
R149  2.2R  [R0402]  125.73 79.93 270 top
R150  2.2R  [R0402]  122.68 79.93 270 top
R151  2.2R  [R0402]  123.7 79.93 270 top
R152  2.2R  [R0402]  126.75 79.93 270 top
R153  2.2R  [R0402]  127.76 79.93 270 top
R154  1K  [R0402]  122.17 97.71 270 bottom
R155  3.4K  [R0402]  123.32 93.01 270 bottom
R156  1K  [R0402]  126.75 97.71 270 bottom
R157  3.4K  [R0402]  127.89 93.01 270 bottom
R158  10K  [R0402]  23.11 89.96 0 top
R159  15K  [R0402]  23.11 89.96 180 bottom
R160  100R  [R0402]  25.91 96.82 90 bottom
R161  1K  [R0402]  27.94 89.45 270 bottom
R162  3.4K  [R0402]  26.8 89.45 90 bottom
R163  2.7K  [R0402]  103.5 93.39 180 bottom
R164  100K  [R0402]  103.5 94.92 180 bottom
R165  100K  [R0402]  103.5 97.07 180 bottom
R166  10K  [R0402]  100.97 94.92 0 bottom
R167  NC  [R0402]  147.96 68.25 0 bottom
R168  1K  [R0402]  109.6 98.34 0 bottom
R169  10K  [R0402]  114.55 98.34 180 bottom
R170  1K  [R0402]  121.54 79.93 270 top
R171  3.4K  [R0402]  113.79 79.29 180 top
R172  1K  [R0402]  61.98 77.52 180 top
R173  1M  [R0805]  68.71 97.07 90 bottom
R174  1K  [R0402]  141.1 57.58 0 top
R175  3.4K  [R0402]  148.08 59.61 0 top
R176  100K  [R0402]  59.82 77.52 0 top
R177  0R  [R0402]  61.47 83.23 0 bottom
R178  10K  [R0402]  58.17 71.67 180 bottom
R179  4.7K  [R0402]  58.17 76.25 180 bottom
R180  27K  [R0402]  54.61 71.67 180 bottom
R181  10K  [R0402]  61.47 71.67 180 bottom
R182  4.7K  [R0402]  61.47 76.25 0 bottom
R183  1M  [R0805]  86.92 97.07 90 bottom
R184  NC  [R0402]  59.18 48.05 0 top
R185  1K  [R0402]  141.1 68.88 0 top
R186  3.4K  [R0402]  148.08 71.04 0 top
R187  NC  [R0402]  148.08 20.75 180 top
R188  NC  [R0402]  148.08 22.14 180 top
R189  1K  [R0402]  141.1 14.27 180 top
R190  3.4K  [R0402]  148.08 16.3 0 top
R191  1K  [R0402]  98.81 25.95 180 top
R192  3.4K  [R0402]  98.81 23.54 180 bottom
R193  10K  [R0402]  106.43 20.37 0 top
R194  10K  [R0402]  106.43 19.35 0 top
R195  1K  [R0402]  141.1 60.88 0 top
R196  3.4K  [R0402]  148.08 63.93 0 top
R197  3.4K  [R0402]  148.08 67.99 0 top
R198  3.4K  [R0402]  148.08 42.08 0 top
R199  3.4K  [R0402]  144.4 46.15 180 top
R200  1K  [R0402]  141.1 39.04 180 top
R201  115K  [R0402]  118.62 20.11 270 top
R202  10K  [R0402]  119.63 20.11 270 top
R203  20K  [R0402]  116.59 20.11 270 top
R204  0R  [R0402]  148.08 72.06 0 top
R205  10K  [R0402]  135 11.48 180 top
R206  1K  [R0402]  135 6.27 180 bottom
R207  10K  [R0402]  135 6.27 0 top
R208  0R  [R0402]  148.08 48.36 0 top
R209  1K  [R0402]  120.65 20.11 270 top
R210  10K  [R0402]  37.97 85.01 180 bottom
R211  20R  [R0603]  40.64 94.28 180 bottom
R212  0R  [R0402]  37.97 96.82 0 bottom
R213  120R  [R0402]  39.37 77.39 0 bottom
R214  2.2K  [R0402]  41.4 76.37 0 bottom
R215  2.2K  [R0402]  46.61 76.37 0 bottom
R216  0R  [R0402]  40.64 96.82 180 bottom
R217  0R  [R0402]  35.18 74.85 90 bottom
R218  0R  [R0402]  34.16 74.85 90 bottom
R219  49.9K  [R0402]  27.81 70.28 270 bottom
R220  10K  [R0402]  28.83 70.28 90 bottom
R221  22R  [R0402]  138.94 75.36 0 top
R222  NC  [R0402]  147.96 67.23 0 bottom
R223  NC  [R0402]  148.08 46.15 0 top
R224  NC  [R0402]  148.08 47.24 0 top
R225  180K  [R0402]  3.94 67.48 0 bottom
R226  NC  [R0402]  147.93 58.52 0 bottom
R227  NC  [R0402]  147.93 59.54 0 bottom
R228  NC  [R0402]  147.93 65.15 0 bottom
R229  NC  [R0402]  147.93 64.14 0 bottom
R230  0R  [R0402]  147.96 72.22 0 bottom
R231  0R  [R0402]  147.96 73.24 0 bottom
R232  0R  [R0402]  147.96 74.72 0 bottom
R233  0R  [R0402]  147.96 75.74 0 bottom
R234  10K  [R0402]  29.46 75.23 180 bottom
R235  115K  [R0402]  3.94 73.71 270 top
R236  1K  [R0402]  3.94 76.88 90 bottom
R237  20K  [R0402]  2.92 73.71 270 top
R238  NC  [R0402]  79.63 48.05 0 top
SS1  -  [NPTH_M3]  3.5 8.5 0 top
SS2  -  [NPTH_M3]  154.5 96.5 0 top
SS3  -  [NPTH_M3]  154.5 8.5 0 top
SS4  -  [NPTH_M3]  3.5 96.5 0 top
SS5  M2X3mm  [T3R2-5R2_TOPSMT]  104.8 48.59 0 top
SS6  M2X3mm  [T3R2-5R2_TOPSMT]  104.8 24.44 0 top
SS7  M2X3mm  [T3R2-5R2_TOPSMT]  129 24.44 0 top
SS8  M2X3mm  [T3R2-5R2_TOPSMT]  129 48.59 0 top
SS9  M3X3.5mm  [SMTSO-M3]  145.9 8.57 0 top
SS10  M2.5X3mm  [SMTSO-M2R5]  92.18 25.2 0 top
SS11  M2.5X3mm  [SMTSO-M2R5]  17.38 25.2 0 top
SW1  TS-1091B-A5B3-D2  [SW_TH_3P_4R5X5R5]  9.4 9.08 0 top
SW2  TS-1091B-A5B3-D2  [SW_TH_3P_4R5X5R5]  14.9 9.08 0 top
SW3  TS-1091B-A5B3-D2  [SW_TH_3P_4R5X5R5]  20.4 9.08 0 top
U1  TP6327GS6  [SOT23_6_B]  3.94 53.51 90 top
U2  TP6327GS6  [SOT23_6_B]  3.94 39.54 90 top
U3  IRM-V838M3-C/TR1  [SMD4-6R80X2R50]  147.5 97.49 0 top
U4  74LVC1G125GW  [SOT-353]  6.61 25.19 180 top
U5  TP6327GS6  [SOT23_6_B]  3.94 67.48 90 top
U6  W25Q32JWSSIQ  [SOIC8-208]  27.69 32.86 0 top
U7  TP6327GS6  [SOT23_6_B]  122.81 62.66 180 top
U8  MAX3485  [SOP8]  52.07 21.76 270 top
U9  TJA1042T  [SOP8]  35.18 21.76 270 top
U10  TJA1042T  [SOP8]  27.69 21.76 270 top
U11  MAX3232CSE  [SOIC16]  68.96 21.64 90 top
U12  74LVC1G125GW  [SOT-353]  2.42 25.19 180 top
U13  MAX3485  [SOP8]  44.45 21.76 270 top
U14  SIM-7-1  [NANO_SIM]  149.68 40.56 270 bottom
U15  NUP5120X6T1G  [SOT563]  139.7 40.33 180 bottom
U16  TP6327GS6  [SOT23_6_B]  3.94 77.01 180 top
U17  RX8010SJ  [SOP-8]  16 81.96 180 bottom
U18  JL2101-N040C  [QFP_40P_R]  67.31 48.56 270 top
U19  JL2101-N040C  [QFP_40P_R]  87.76 48.56 270 top
U20  TP6327GS6  [SOT23_6_B]  137.29 60.88 270 top
U21  PI6C557-05BLE  [TSSOP20]  144.4 76.25 270 top
U22  RCLAMP0524P  [USON_10]  128.27 82.09 0 top
U23  RCLAMP0524P  [USON_10]  124.21 82.09 0 top
U24  MT9700  [SOT23-5]  124.46 96.69 180 bottom
U25  MT9700  [SOT23-5]  27.94 86.66 90 bottom
U26  MT9700  [SOT23-5]  129.03 96.69 180 bottom
U28  FE1.1s-BQFN24B  [QFN24]  107.7 94.66 180 bottom
U29  MT9700  [SOT23-5]  117.47 80.44 270 top
U30  RCLAMP0524P  [USON_10]  107.06 90.85 0 bottom
U31  RCLAMP0524P  [USON_10]  50.42 77.39 0 top
U32  RCLAMP0524P  [USON_10]  54.36 77.39 0 top
U33  MT9700  [SOT23-5]  144.4 58.47 90 top
U34  MT9700  [SOT23-5]  144.4 61.77 90 top
U35  MT9700  [SOT23-5]  144.4 65.83 90 top
U36  MT9700  [SOT23-5]  144.4 69.77 90 top
U37  MT9700  [SOT23-5]  144.4 15.16 90 top
U38  MT9700  [SOT23-5]  98.81 22.65 90 top
U39  MT9700  [SOT23-5]  144.4 39.92 90 top
U40  MT9700  [SOT23-5]  144.4 43.99 90 top
U41  TP6327GS6  [SOT23_6_B]  117.47 23.54 180 top
Y1  25MHz  [3225]  135.76 75.87 270 top
Y2  12MHz  [3225]  114.68 95.68 270 bottom
Y3  25MHz  [3225]  76.45 49.96 270 top
Y4  25MHz  [3225]  97.16 49.96 270 top
Z1  PESD3V3L1BA  [SOD323]  5.46 16.18 180 bottom
Z2  PESD3V3L1BA  [SOD323]  5.46 18.84 180 bottom

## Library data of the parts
C1-C4 C6-C52 C55-C122 C129-C176 C179-C213 C216-C218 = CAP_NP
C5 C214 C215 = CAP
C53 C54 C177 C178 = CAP_NP: signal model: CAP_NP_C0402_DISCRETE_0.1UF_0.1uF
C123-C128 = CAP_NP: signal model: CAP_NP_C0402_DISCRETE_0.22UF_0.22uF
D1-D3 D6-D13 D15-D19 D23-D26 D28-D34 Z1 Z2 = DIODE BI-DIR TRIG
D4 D5 D14 D22 D35 = DIODE_SCHTKY
D20 = DIODE
D21 = BAT54C
D27 = BAT54A
F1 = FUSE
J1 J5 J10 = CON4
J2 = 1X3PIN
J3 J15 J28 = 1X6PIN
J4 = TF_Card
J6 = A1501WV-2P
J8 = CON6
J9 J12 = 1X4PIN
J11 J18 = HY911130A
J13 J14 = 2X3PIN
J16 = 1.25T-2A
J17 = M2_NGFF_M_KEY
J19 = USB3D0_USB2D0-A-D
J20 = USB-A-D
J21 = HDMI-001C
J22 J24 = FPC_24P_0P5
J23 J26 J29 = FPC-05F-30PH20
J25 J27 = MIC_JACK
J30 J31 = 1X2PIN
J32 J33 = TEST
J34 = SATA
J35 = MINI-PCIE
J36 = TYPE-C-31-M-12
J38 = AS0B821-S55B-7H
J39 = DC-044A-20A
L1 L3 L4 L8 L9 L13 L17 L22 L35 = IND
L2 L5-L7 L10-L12 L14-L16 L19-L21 = BEAD
LED1 LED2 = LED
Q1 Q2 Q6-Q8 Q14 = 2SK3018
Q3 Q10 = MOSFET_P
Q4 = NPN
R1-R28 R31-R33 R35-R50 R55 R56 R58 R59 R61-R63 R67-R76 R79-R86 R88-R90 R97-R110 R112-R117 R121 R125-R144 R146 R147 R154-R220 R222-R225 R234-R238 = RES
R29 R30 R34 R51-R54 R57 R60 R66 R91-R96 R118-R120 R122-R124 R221 = RES: signal model: RES_R0402_DISCRETE_22R_22R
R64 R65 R145 R148-R153 = RES: signal model: RES_R0402_DISCRETE_2.2R_2.2R
R77 R78 R87 R111 = RES: signal model: RES_R0402_DISCRETE_33R_33R
R226-R229 = RES: signal model: RES_R0402_DISCRETE_NC_NC
R230-R233 = RES: signal model: RES_R0402_DISCRETE_0R_0R
SS1-SS11 = SPACER
SW1-SW3 = SW_TH3P
U1 U2 U5 U7 U16 U20 U41 = TP6327GS6
U3 = IRM-V838M3-C/TR1
U4 U12 = 74LVC1G125
U6 = W25QXX_8P
U8 U13 = TJA1057GT3
U9 U10 = TJA1057GT3_8P
U11 = MAX3232CSE
U14 = SIM-7-1
U15 = NUP5120-D
U17 = RX8010SJ
U18 U19 = RTL8211F
U21 = PI6C557-05BLE
U22 U23 U30 U31 = RCLAMP0524P
U24-U26 U29 U33-U40 = MT9700
U28 = FE1.1s-BQFN24B
U32 = RCLAMP0524P: signal model: RCLAMP0524P_USON_10_RCLAMP0524P_RCLAMP0524P
Y1-Y4 = CRYSTAL_4P

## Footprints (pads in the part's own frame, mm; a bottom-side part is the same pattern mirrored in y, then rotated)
3225
  rect 1.3x1 smd: 1(-1.15,-0.75) 2(1.15,-0.75) 3(1.15,0.75) 4(-1.15,0.75)
AS0B821-S55B-7H
  round 1.1 hole 1.1 unplated: (-41,0.25)
  round 1.6 hole 1.6: (41,0.25)
  rect 0.3x2 smd: 1(-40,-3.95) 2(-39.75,3.95) 3(-39.5,-3.95) 4(-39.25,3.95) 5(-39,-3.95) 6(-38.75,3.95) 7(-38.5,-3.95) 8(-38.25,3.95) 9(-38,-3.95) 10(-37.75,3.95) 11(-37.5,-3.95) 12(-37.25,3.95) 13(-37,-3.95) 14(-36.75,3.95) 15(-36.5,-3.95) 16(-36.25,3.95) 17(-36,-3.95) 18(-35.75,3.95) 19(-35.5,-3.95) 20(-35.25,3.95) 21(-35,-3.95) 22(-34.75,3.95) 23(-34.5,-3.95) 24(-34.25,3.95) 25(-34,-3.95) 26(-33.75,3.95) 27(-33.5,-3.95) 28(-33.25,3.95) 29(-33,-3.95) 30(-32.75,3.95) 31(-32.5,-3.95) 32(-32.25,3.95) 33(-32,-3.95) 34(-31.75,3.95) 35(-31.5,-3.95) 36(-31.25,3.95) 37(-31,-3.95) 38(-30.75,3.95) 39(-30.5,-3.95) 40(-30.25,3.95) 41(-30,-3.95) 42(-29.75,3.95) 43(-29.5,-3.95) 44(-29.25,3.95) 45(-29,-3.95) 46(-28.75,3.95) 47(-28.5,-3.95) 48(-28.25,3.95) 49(-28,-3.95) 50(-27.75,3.95) 51(-27.5,-3.95) 52(-27.25,3.95) 53(-27,-3.95) 54(-26.75,3.95) 55(-26.5,-3.95) 56(-26.25,3.95) 57(-26,-3.95) 58(-25.75,3.95) 59(-25.5,-3.95) 60(-25.25,3.95) 61(-25,-3.95) 62(-24.75,3.95) 63(-24.5,-3.95) 64(-24.25,3.95) 65(-24,-3.95) 66(-23.75,3.95) 67(-23.5,-3.95) 68(-23.25,3.95) 69(-23,-3.95) 70(-22.75,3.95) 71(-22.5,-3.95) 72(-22.25,3.95) 73(-22,-3.95) 74(-21.75,3.95) 75(-21.5,-3.95) 76(-21.25,3.95) 77(-21,-3.95) 78(-20.75,3.95) 79(-20.5,-3.95) 80(-20.25,3.95) 81(-20,-3.95) 82(-19.75,3.95) 83(-19.5,-3.95) 84(-19.25,3.95) 85(-19,-3.95) 86(-18.75,3.95) 87(-18.5,-3.95) 88(-18.25,3.95) 89(-18,-3.95) 90(-17.75,3.95) 91(-17.5,-3.95) 92(-17.25,3.95) 93(-17,-3.95) 94(-16.75,3.95) 95(-16.5,-3.95) 96(-16.25,3.95) 97(-16,-3.95) 98(-15.75,3.95) 99(-15.5,-3.95) 100(-15.25,3.95) 101(-15,-3.95) 102(-14.75,3.95) 103(-14.5,-3.95) 104(-14.25,3.95) 105(-14,-3.95) 106(-13.75,3.95) 107(-13.5,-3.95) 108(-13.25,3.95) 109(-13,-3.95) 110(-12.75,3.95) 111(-12.5,-3.95) 112(-12.25,3.95) 113(-12,-3.95) 114(-11.75,3.95) 115(-11.5,-3.95) 116(-11.25,3.95) 117(-11,-3.95) 118(-10.75,3.95) 119(-10.5,-3.95) 120(-10.25,3.95) 121(-10,-3.95) 122(-9.75,3.95) 123(-9.5,-3.95) 124(-9.25,3.95) 125(-9,-3.95) 126(-8.75,3.95) 127(-8.5,-3.95) 128(-8.25,3.95) 129(-8,-3.95) 130(-7.75,3.95) 131(-7.5,-3.95) 132(-7.25,3.95) 133(-7,-3.95) 134(-6.75,3.95) 135(-6.5,-3.95) 136(-6.25,3.95) 137(-6,-3.95) 138(-5.75,3.95) 139(-5.5,-3.95) 140(-5.25,3.95) 141(-5,-3.95) 142(-4.75,3.95) 143(-4.5,-3.95) 144(-4.25,3.95) 145(-4,-3.95) 146(-3.75,3.95) 147(-3.5,-3.95) 148(-3.25,3.95) 149(-3,-3.95) 150(-2.75,3.95) 151(-2.5,-3.95) 152(-2.25,3.95) 153(-2,-3.95) 154(-1.75,3.95) 155(-1.5,-3.95) 156(-1.25,3.95) 157(-1,-3.95) 158(-0.75,3.95) 159(-0.5,-3.95) 160(-0.25,3.95) 161(0,-3.95) 162(0.25,3.95) 163(0.5,-3.95) 164(0.75,3.95) 165(1,-3.95) 166(3.25,3.95) 167(3,-3.95) 168(3.75,3.95) 169(3.5,-3.95) 170(4.25,3.95) 171(4,-3.95) 172(4.75,3.95) 173(4.5,-3.95) 174(5.25,3.95) 175(5,-3.95) 176(5.75,3.95) 177(5.5,-3.95) 178(6.25,3.95) 179(6,-3.95) 180(6.75,3.95) 181(6.5,-3.95) 182(7.25,3.95) 183(7,-3.95) 184(7.75,3.95) 185(7.5,-3.95) 186(8.25,3.95) 187(8,-3.95) 188(8.75,3.95) 189(8.5,-3.95) 190(9.25,3.95) 191(9,-3.95) 192(9.75,3.95) 193(9.5,-3.95) 194(10.25,3.95) 195(10,-3.95) 196(10.75,3.95) 197(10.5,-3.95) 198(11.25,3.95) 199(11,-3.95) 200(11.75,3.95) 201(11.5,-3.95) 202(12.25,3.95) 203(12,-3.95) 204(12.75,3.95) 205(12.5,-3.95) 206(13.25,3.95) 207(13,-3.95) 208(13.75,3.95) 209(13.5,-3.95) 210(14.25,3.95) 211(14,-3.95) 212(14.75,3.95) 213(14.5,-3.95) 214(15.25,3.95) 215(15,-3.95) 216(15.75,3.95) 217(15.5,-3.95) 218(16.25,3.95) 219(16,-3.95) 220(16.75,3.95) 221(16.5,-3.95) 222(17.25,3.95) 223(17,-3.95) 224(17.75,3.95) 225(17.5,-3.95) 226(18.25,3.95) 227(18,-3.95) 228(18.75,3.95) 229(18.5,-3.95) 230(19.25,3.95) 231(19,-3.95) 232(19.75,3.95) 233(19.5,-3.95) 234(20.25,3.95) 235(20,-3.95) 236(20.75,3.95) 237(20.5,-3.95) 238(21.25,3.95) 239(21,-3.95) 240(21.75,3.95) 241(21.5,-3.95) 242(22.25,3.95) 243(22,-3.95) 244(22.75,3.95) 245(22.5,-3.95) 246(23.25,3.95) 247(23,-3.95) 248(23.75,3.95) 249(23.5,-3.95) 250(24.25,3.95) 251(24,-3.95) 252(24.75,3.95) 253(24.5,-3.95) 254(25.25,3.95) 255(25,-3.95) 256(25.75,3.95) 257(25.5,-3.95) 258(26.25,3.95) 259(26,-3.95) 260(26.75,3.95) 261(26.5,-3.95) 262(27.25,3.95) 263(27,-3.95) 264(27.75,3.95) 265(27.5,-3.95) 266(28.25,3.95) 267(28,-3.95) 268(28.75,3.95) 269(28.5,-3.95) 270(29.25,3.95) 271(29,-3.95) 272(29.75,3.95) 273(29.5,-3.95) 274(30.25,3.95) 275(30,-3.95) 276(30.75,3.95) 277(30.5,-3.95) 278(31.25,3.95) 279(31,-3.95) 280(31.75,3.95) 281(31.5,-3.95) 282(32.25,3.95) 283(32,-3.95) 284(32.75,3.95) 285(32.5,-3.95) 286(33.25,3.95) 287(33,-3.95) 288(33.75,3.95) 289(33.5,-3.95) 290(34.25,3.95) 291(34,-3.95) 292(34.75,3.95) 293(34.5,-3.95) 294(35.25,3.95) 295(35,-3.95) 296(35.75,3.95) 297(35.5,-3.95) 298(36.25,3.95) 299(36,-3.95) 300(36.75,3.95) 301(36.5,-3.95) 302(37.25,3.95) 303(37,-3.95) 304(37.75,3.95) 305(37.5,-3.95) 306(38.25,3.95) 307(38,-3.95) 308(38.75,3.95) 309(38.5,-3.95) 310(39.25,3.95) 311(39,-3.95) 312(39.75,3.95) 313(39.5,-3.95) 314(40,-3.95)
  rect 3x5.15 smd: 315(43.4,1) 316(-43.4,1)
C0402
  rect 0.599x0.599 smd: 1(-0.5,0) 2(0.5,0)
C0603
  rect 0.8x0.8 smd: 1(-0.8,0) 2(0.8,0)
C0805
  rect 1.16x1.47 smd: 1(-0.89,0) 2(0.89,0)
DB2ERC-3P81-4P
  rect 1.83x1.83 hole 1.23: 1(-5.715,0)
  round 1.83 hole 1.23: 2(-1.905,0) 3(1.905,0) 4(5.715,0)
DB2ERC-3P81-6P
  rect 1.8x1.8 hole 1.2: 1(-9.525,0)
  round 1.8 hole 1.2: 2(-5.715,0) 3(-1.905,0) 4(1.905,0) 5(5.715,0) 6(9.525,0)
DC_IN_TH_3P_10R1X11R6
  round 1.9 hole 1.9 unplated: (-2.575,-1.3)
  oval 3x1.6 hole 2.2x1: 1(-3.625,-4.9) 2(3.625,-1.3) 3(3.625,4) 4(3.625,-4.5) 5(-3.625,4.9)
DIP-2X3-2P54
  rect 1.5x1.5 hole 0.9: 1(-2.54,-1.27)
  round 1.5 hole 0.9: 2(-2.54,1.27) 3(0,-1.27) 4(0,1.27) 5(2.54,-1.27) 6(2.54,1.27)
DIP_3P_2P54
  rect 1.5x1.5 hole 0.9: 1(-2.54,0)
  round 1.5 hole 0.9: 2(0,0) 3(2.54,0)
EAR_JACK
  oval 2.184x2.489 hole 1.575: 1(5.6,0) 2(-3.7,2) 3(1.9,2) 4(0,0) 5(-6.2,0)
EC6P3
  rect 1.001x1.999 smd: 1(0,2.8) 2(0,-2.8)
ES0402
  rect 0.599x0.599 smd: 1(-0.5,0) 2(0.5,0)
F1812
  rect 1.78x3.3 smd: 1(-2.305,0) 2(2.305,0)
FPC-30P-0P5
  rect 0.3x1.3 smd: 1(-7.25,1.35) 2(-6.75,1.35) 3(-6.25,1.35) 4(-5.75,1.35) 5(-5.25,1.35) 6(-4.75,1.35) 7(-4.25,1.35) 8(-3.75,1.35) 9(-3.25,1.35) 10(-2.75,1.35) 11(-2.25,1.35) 12(-1.75,1.35) 13(-1.25,1.35) 14(-0.75,1.35) 15(-0.25,1.35) 16(0.25,1.35) 17(0.75,1.35) 18(1.25,1.35) 19(1.75,1.35) 20(2.25,1.35) 21(2.75,1.35) 22(3.25,1.35) 23(3.75,1.35) 24(4.25,1.35) 25(4.75,1.35) 26(5.25,1.35) 27(5.75,1.35) 28(6.25,1.35) 29(6.75,1.35) 30(7.25,1.35)
  rect 1.6x2 smd: 31(9.4,-1.35) 32(-9.4,-1.35)
FPC_24P_0P5
  rect 0.3x1.3 smd: 1(-5.75,-1.351) 2(-5.25,-1.351) 3(-4.75,-1.351) 4(-4.25,-1.351) 5(-3.75,-1.351) 6(-3.25,-1.351) 7(-2.75,-1.351) 8(-2.25,-1.351) 9(-1.75,-1.351) 10(-1.25,-1.351) 11(-0.75,-1.351) 12(-0.25,-1.351) 13(0.25,-1.351) 14(0.75,-1.351) 15(1.25,-1.351) 16(1.75,-1.351) 17(2.25,-1.351) 18(2.75,-1.351) 19(3.25,-1.351) 20(3.75,-1.351) 21(4.25,-1.351) 22(4.75,-1.351) 23(5.25,-1.351) 24(5.75,-1.351)
  rect 1.6x2 smd: 25(7.45,1.351) 26(-7.45,1.351)
GH1P25_TH_2P
  rect 0.9x0.9 hole 0.5: 1(-0.625,0)
  round 0.9 hole 0.5: 2(0.625,0)
HDMI-SMD
  round 2 hole 2 unplated: (-6.05,-2) (7.2,1.5)
  round 0.8 hole 0.55: 1(5.3,0.5) 2(4.731,-0.5) 3(4.145,0.5) 4(3.575,-0.5) 5(2.99,0.5) 6(2.419,-0.5) 7(1.835,0.5) 8(1.263,-0.5) 9(0.68,0.5) 10(0.107,-0.5) 11(-0.475,0.5) 12(-1.049,-0.5) 13(-1.63,0.5) 14(-2.205,-0.5) 15(-2.785,0.5) 16(-3.361,-0.5) 17(-3.94,0.5) 18(-4.517,-0.5) 19(-5.095,0.5)
  oval 3.2x1.4 hole 2.7x0.9: G1(-6.05,3.25) G2(3.45,3.25) G3(-2.95,-3.25) G4(6.05,-3.25)
HY911130A
  round 3.25 hole 3.25 unplated: (-5.715,0) (5.715,0)
  round 1.6 hole 1: 1(5.72,-8.89) 2(4.45,-6.35) 3(3.18,-8.89) 4(1.91,-6.35) 5(0.64,-8.89) 6(-0.63,-6.35) 7(-1.9,-8.89) 8(-3.17,-6.35) 9(-4.44,-8.89) 10(-5.71,-6.35)
  round 1.8 hole 1.2: 11(6.625,4.9) 12(4.085,4.9) 13(-4.085,4.9) 14(-6.625,4.9)
  round 2.43 hole 1.83: 15(7.745,-3.05) 16(-7.745,-3.05)
L0603
  rect 0.889x0.889 smd: 1(-0.8,0) 2(0.8,0)
L2520
  rect 1.118x2.032 smd: 1(-0.959,0) 2(0.959,0)
L4520
  rect 1.4x2.3 smd: 1(-1.8,0) 2(1.8,0)
LED_HS_0602_UR
  rect 0.77x0.6 smd: 1(0.815,0) 2(-0.815,0)
M2_NGFF_M_KEY
  round 1.1 hole 1.1 unplated: (-10,-1.475)
  round 1.6 hole 1.6 unplated: (10,-1.475)
  rect 0.3x1.55 smd: 1(-9.25,3.725) 2(-9,-3.725) 3(-8.75,3.725) 4(-8.5,-3.725) 5(-8.25,3.725) 6(-8,-3.725) 7(-7.75,3.725) 8(-7.5,-3.725) 9(-7.25,3.725) 10(-7,-3.725) 11(-6.75,3.725) 12(-6.5,-3.725) 13(-6.25,3.725) 14(-6,-3.725) 15(-5.75,3.725) 16(-5.5,-3.725) 17(-5.25,3.725) 18(-5,-3.725) 19(-4.75,3.725) 20(-4.5,-3.725) 21(-4.25,3.725) 22(-4,-3.725) 23(-3.75,3.725) 24(-3.5,-3.725) 25(-3.25,3.725) 26(-3,-3.725) 27(-2.75,3.725) 28(-2.5,-3.725) 29(-2.25,3.725) 30(-2,-3.725) 31(-1.75,3.725) 32(-1.5,-3.725) 33(-1.25,3.725) 34(-1,-3.725) 35(-0.75,3.725) 36(-0.5,-3.725) 37(-0.25,3.725) 38(0,-3.725) 39(0.25,3.725) 40(0.5,-3.725) 41(0.75,3.725) 42(1,-3.725) 43(1.25,3.725) 44(1.5,-3.725) 45(1.75,3.725) 46(2,-3.725) 47(2.25,3.725) 48(2.5,-3.725) 49(2.75,3.725) 50(3,-3.725) 51(3.25,3.725) 52(3.5,-3.725) 53(3.75,3.725) 54(4,-3.725) 55(4.25,3.725) 56(4.5,-3.725) 57(4.75,3.725) 58(5,-3.725) 67(7.25,3.725) 68(7.5,-3.725) 69(7.75,3.725) 70(8,-3.725) 71(8.25,3.725) 72(8.5,-3.725) 73(8.75,3.725) 74(9,-3.725) 75(9.25,3.725)
  rect 1.2x2.75 smd: 76(10.35,3.025) 77(-10.35,3.025)
NANO_SIM
  round 0.9 hole 0.9 unplated: (-5,-5.49) (3.5,-5.49)
  rect 0.5x1.3 smd: 1(0.25,6.74) 2(-2.29,6.74) 3(-4.83,6.74) 4(2.47,6.74) 5(1.52,6.74) 6(-1.02,6.74) 7(-3.56,6.74)
  rect 1x2.1 smd: 8(-6.5,5.26) 9(6.5,5.26) 10(-6.5,-6.74) 11(6.5,-6.74)
NPTH_M3
  round 3.2 hole 3.2 unplated: (0,0)
PCIE_52P
  round 1.6 hole 1.6 unplated: (-12.5,0)
  round 1.1 hole 1.1 unplated: (12.5,0)
  rect 0.6x2 smd: 1(-11.8,-4.1) 2(-11.4,4.1) 3(-11,-4.1) 4(-10.6,4.1) 5(-10.2,-4.1) 6(-9.8,4.1) 7(-9.4,-4.1) 8(-9,4.1) 9(-8.6,-4.1) 10(-8.2,4.1) 11(-7.8,-4.1) 12(-7.4,4.1) 13(-7,-4.1) 14(-6.6,4.1) 15(-6.2,-4.1) 16(-5.8,4.1) 17(-2.2,-4.1) 18(-1.8,4.1) 19(-1.4,-4.1) 20(-1,4.1) 21(-0.6,-4.1) 22(-0.2,4.1) 23(0.2,-4.1) 24(0.6,4.1) 25(1,-4.1) 26(1.4,4.1) 27(1.8,-4.1) 28(2.2,4.1) 29(2.6,-4.1) 30(3,4.1) 31(3.4,-4.1) 32(3.8,4.1) 33(4.2,-4.1) 34(4.6,4.1) 35(5,-4.1) 36(5.4,4.1) 37(5.8,-4.1) 38(6.2,4.1) 39(6.6,-4.1) 40(7,4.1) 41(7.4,-4.1) 42(7.8,4.1) 43(8.2,-4.1) 44(8.6,4.1) 45(9,-4.1) 46(9.4,4.1) 47(9.8,-4.1) 48(10.2,4.1) 49(10.6,-4.1) 50(11,4.1) 51(11.4,-4.1) 52(11.8,4.1)
  rect 2.15x2.6 smd: 53(14.65,-3.5) 54(-14.65,-3.5)
PH-1X2-2P0_L
  rect 1.1x1.1 hole 0.7: 1(-1,0)
  round 1.1 hole 0.7: 2(1,0)
PH-1X4-2P0
  rect 1.1x1.1 hole 0.7: 1(-3,0)
  round 1.1 hole 0.7: 2(-1,0) 3(1,0) 4(3,0)
PH-1X6-2P0
  rect 1.1x1.1 hole 0.7: 1(-5,0)
  round 1.1 hole 0.7: 2(-3,0) 3(-1,0) 4(1,0) 5(3,0) 6(5,0)
QFN24
  rect 1x0.3 smd: 1(-2.1,1.25) 2(-2.1,0.75) 3(-2.1,0.25) 4(-2.1,-0.25) 5(-2.1,-0.75) 6(-2.1,-1.25) 13(2.1,-1.25) 14(2.1,-0.75) 15(2.1,-0.25) 16(2.1,0.25) 17(2.1,0.75) 18(2.1,1.25)
  rect 0.3x1 smd: 7(-1.25,-2.1) 8(-0.75,-2.1) 9(-0.25,-2.1) 10(0.25,-2.1) 11(0.75,-2.1) 12(1.25,-2.1) 19(1.25,2.1) 20(0.75,2.1) 21(0.25,2.1) 22(-0.25,2.1) 23(-0.75,2.1) 24(-1.25,2.1)
  rect 2x2 smd: 25(0,0)
QFP_40P_R
  oval 0.8x0.22 smd: 1(-2.5,1.8) 2(-2.5,1.4) 3(-2.5,1) 4(-2.5,0.6) 5(-2.5,0.2) 6(-2.5,-0.2) 7(-2.5,-0.6) 8(-2.5,-1) 9(-2.5,-1.4) 10(-2.5,-1.8) 21(2.5,-1.8) 22(2.5,-1.4) 23(2.5,-1) 24(2.5,-0.6) 25(2.5,-0.2) 26(2.5,0.2) 27(2.5,0.6) 28(2.5,1) 29(2.5,1.4) 30(2.5,1.8)
  oval 0.22x0.8 smd: 11(-1.8,-2.5) 12(-1.4,-2.5) 13(-1,-2.5) 14(-0.6,-2.5) 15(-0.2,-2.5) 16(0.2,-2.5) 17(0.6,-2.5) 18(1,-2.5) 19(1.4,-2.5) 20(1.8,-2.5) 31(1.8,2.5) 32(1.4,2.5) 33(1,2.5) 34(0.6,2.5) 35(0.2,2.5) 36(-0.2,2.5) 37(-0.6,2.5) 38(-1,2.5) 39(-1.4,2.5) 40(-1.8,2.5)
  rect 3x3 smd: 41(0,0)
R0402
  rect 0.599x0.599 smd: 1(-0.5,0) 2(0.5,0)
R0603
  rect 0.8x0.8 smd: 1(-0.8,0) 2(0.8,0)
R0805
  rect 1.016x1.143 smd: 1(-1.016,0) 2(1.016,0)
SMD4-6R80X2R50
  rect 0.8x1.2 smd: 1(1.905,0) 2(0.635,0) 3(-0.635,0) 4(-1.905,0)
SMTSO-M2R5
  round 6.2 hole 4.22: 1(0,0)
SMTSO-M3
  round 6.2 hole 4.22: 1(0,0)
SOD323
  rect 1x0.83 smd: 1(1.18,0) 2(-1.18,0)
SOD523
  rect 0.64x0.5 smd: 1(0.73,0) 2(-0.73,0)
SOD-123
  rect 1.2x1.4 smd: 1(-1.7,0) 2(1.7,0)
SOIC8-208
  rect 1.778x0.635 smd: 1(-4,1.905) 2(-4,0.635) 3(-4,-0.635) 4(-4,-1.905) 5(4,-1.905) 6(4,-0.635) 7(4,0.635) 8(4,1.905)
SOIC16
  oval 2.032x0.61 smd: 1(-2.789,4.44) 2(-2.789,3.18) 3(-2.789,1.9) 4(-2.789,0.64) 5(-2.789,-0.64) 6(-2.789,-1.9) 7(-2.789,-3.18) 8(-2.789,-4.44) 9(2.789,-4.44) 10(2.789,-3.18) 11(2.789,-1.9) 12(2.789,-0.64) 13(2.789,0.64) 14(2.789,1.9) 15(2.789,3.18) 16(2.789,4.44)
SOP8
  oval 1.651x0.635 smd: 1(-2.6,1.905) 2(-2.6,0.635) 3(-2.6,-0.635) 4(-2.6,-1.905) 5(2.6,-1.905) 6(2.6,-0.635) 7(2.6,0.635) 8(2.6,1.905)
SOP-8
  oval 0.7x1.7 smd: 1(-1.905,-3.1) 2(-0.635,-3.1) 3(0.635,-3.1) 4(1.905,-3.1) 5(1.905,3.1) 6(0.635,3.1) 7(-0.635,3.1) 8(-1.905,3.1)
SOT23
  rect 0.914x0.914 smd: 1(-0.953,-0.991) 2(0.953,-0.991)
  rect 0.914x1.27 smd: 3(0,1.041)
SOT23-5
  rect 0.599x1.199 smd: 1(-0.95,-1.25) 2(0,-1.25) 3(0.95,-1.25) 4(0.95,1.25) 5(-0.95,1.25)
SOT23_6_B
  rect 0.7x0.9 smd: 1(-0.95,-1.2) 2(0,-1.2) 3(0.95,-1.2) 4(0.95,1.2) 5(0,1.2) 6(-0.95,1.2)
SOT563
  rect 0.3x0.45 smd: 1(-0.5,-0.675) 2(0,-0.675) 3(0.5,-0.675) 4(0.5,0.675) 5(0,0.675) 6(-0.5,0.675)
SOT-353
  rect 0.406x1.194 smd: 1(-0.65,-0.9) 2(0,-0.9) 3(0.65,-0.9) 4(0.65,0.9) 5(-0.65,0.9)
SSATA_V
  round 1.1 hole 0.75: 1(-3.81,0) 2(-2.54,-1) 3(-1.27,-1) 4(0,0) 5(1.27,-1) 6(2.54,-1) 7(3.81,0)
  round 2.1 hole 1.5: S1(6.48,-0.5) S2(-6.48,-0.5)
SW_TH_3P_4R5X5R5
  round 1.4 hole 0.8: 1(-1.55,0.975) 2(1.55,0.975) 3(0,-0.975)
T3R2-5R2_TOPSMT
  round 5.2 hole 3.2: 1(0,0)
TFCARD
  round 1.016 hole 1.016 unplated: (-4,0) (4,0)
  rect 0.7x1.6 smd: 1(3.2,10.5) 2(2.1,10.5) 3(1,10.5) 4(-0.1,10.5) 5(-1.2,10.5) 6(-2.3,10.5) 7(-3.4,10.5) 8(-4.5,10.5) 9(-5.6,10.5)
  rect 1.2x1.778 smd: 10(-6.8,10)
  rect 1.524x2.413 smd: 11(-6.8,0.4) 12(8.7,0.4)
  rect 1.778x1.778 smd: 13(7.8,10)
TP_1MM
  round 1.016 smd: 1(0,0)
TSSOP20
  rect 0.4x1.5 smd: 1(-2.925,-3) 2(-2.275,-3) 3(-1.625,-3) 4(-0.975,-3) 5(-0.325,-3) 6(0.325,-3) 7(0.975,-3) 8(1.625,-3) 9(2.275,-3) 10(2.925,-3) 11(2.925,3) 12(2.275,3) 13(1.625,3) 14(0.975,3) 15(0.325,3) 16(-0.325,3) 17(-0.975,3) 18(-1.625,3) 19(-2.275,3) 20(-2.925,3)
TYPE-C-31-M-12
  round 0.65 hole 0.65 unplated: (-2.89,-1.44) (2.89,-1.44)
  rect 0.3x2 smd: A1(-3.35,0.279) A4(-2.55,0.279) A5(-1.25,0.279) A6(-0.249,0.279) A7(0.249,0.279) A8(1.25,0.279) A9(2.55,0.279) A12(3.35,0.279) B1(3.05,0.279) B4(2.25,0.279) B5(1.75,0.279) B6(0.749,0.279) B7(-0.749,0.279) B8(-1.75,0.279) B9(-2.25,0.279) B12(-3.05,0.279)
  oval 1.1x1.7 hole 0.6x1.2: C1(-4.32,-5.1) C2(4.32,-5.1)
  oval 1.1x2.2 hole 0.6x1.7: C3(-4.32,-0.909) C4(4.32,-0.909)
unnamed
  round 1.016 smd: 1(0,0)
USB3D0-AF-18P
  round 1.1 hole 0.701: 1(-3.5,-1.501) 2(-1.001,-1.501) 3(1.001,-1.501) 4(3.5,-1.501) 5(4,0) 6(1.999,0) 7(0,0) 8(-1.999,0) 9(-4,0) 10(-3.5,1.699) 11(-1.001,1.699) 12(1.001,1.699) 13(3.5,1.699) 14(4,3.2) 15(1.999,3.2) 16(0,3.2) 17(-1.999,3.2) 18(-4,3.2)
  round 3.2 hole 2.4: 19(6.571,-3.5) 20(6.571,2.179) 21(-6.571,2.179) 22(-6.571,-3.5)
